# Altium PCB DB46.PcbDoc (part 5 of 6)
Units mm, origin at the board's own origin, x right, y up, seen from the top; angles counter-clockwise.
Board outline 82.2 x 113.2 mm, 8 copper layers (Top Layer, MidLayer1, MidLayer2, GND, MidLayer3, VCC, MidLayer4, Bottom Layer), stack 1.576 mm thick; 186 components, 477 nets, 1727 pads, 1538 vias.
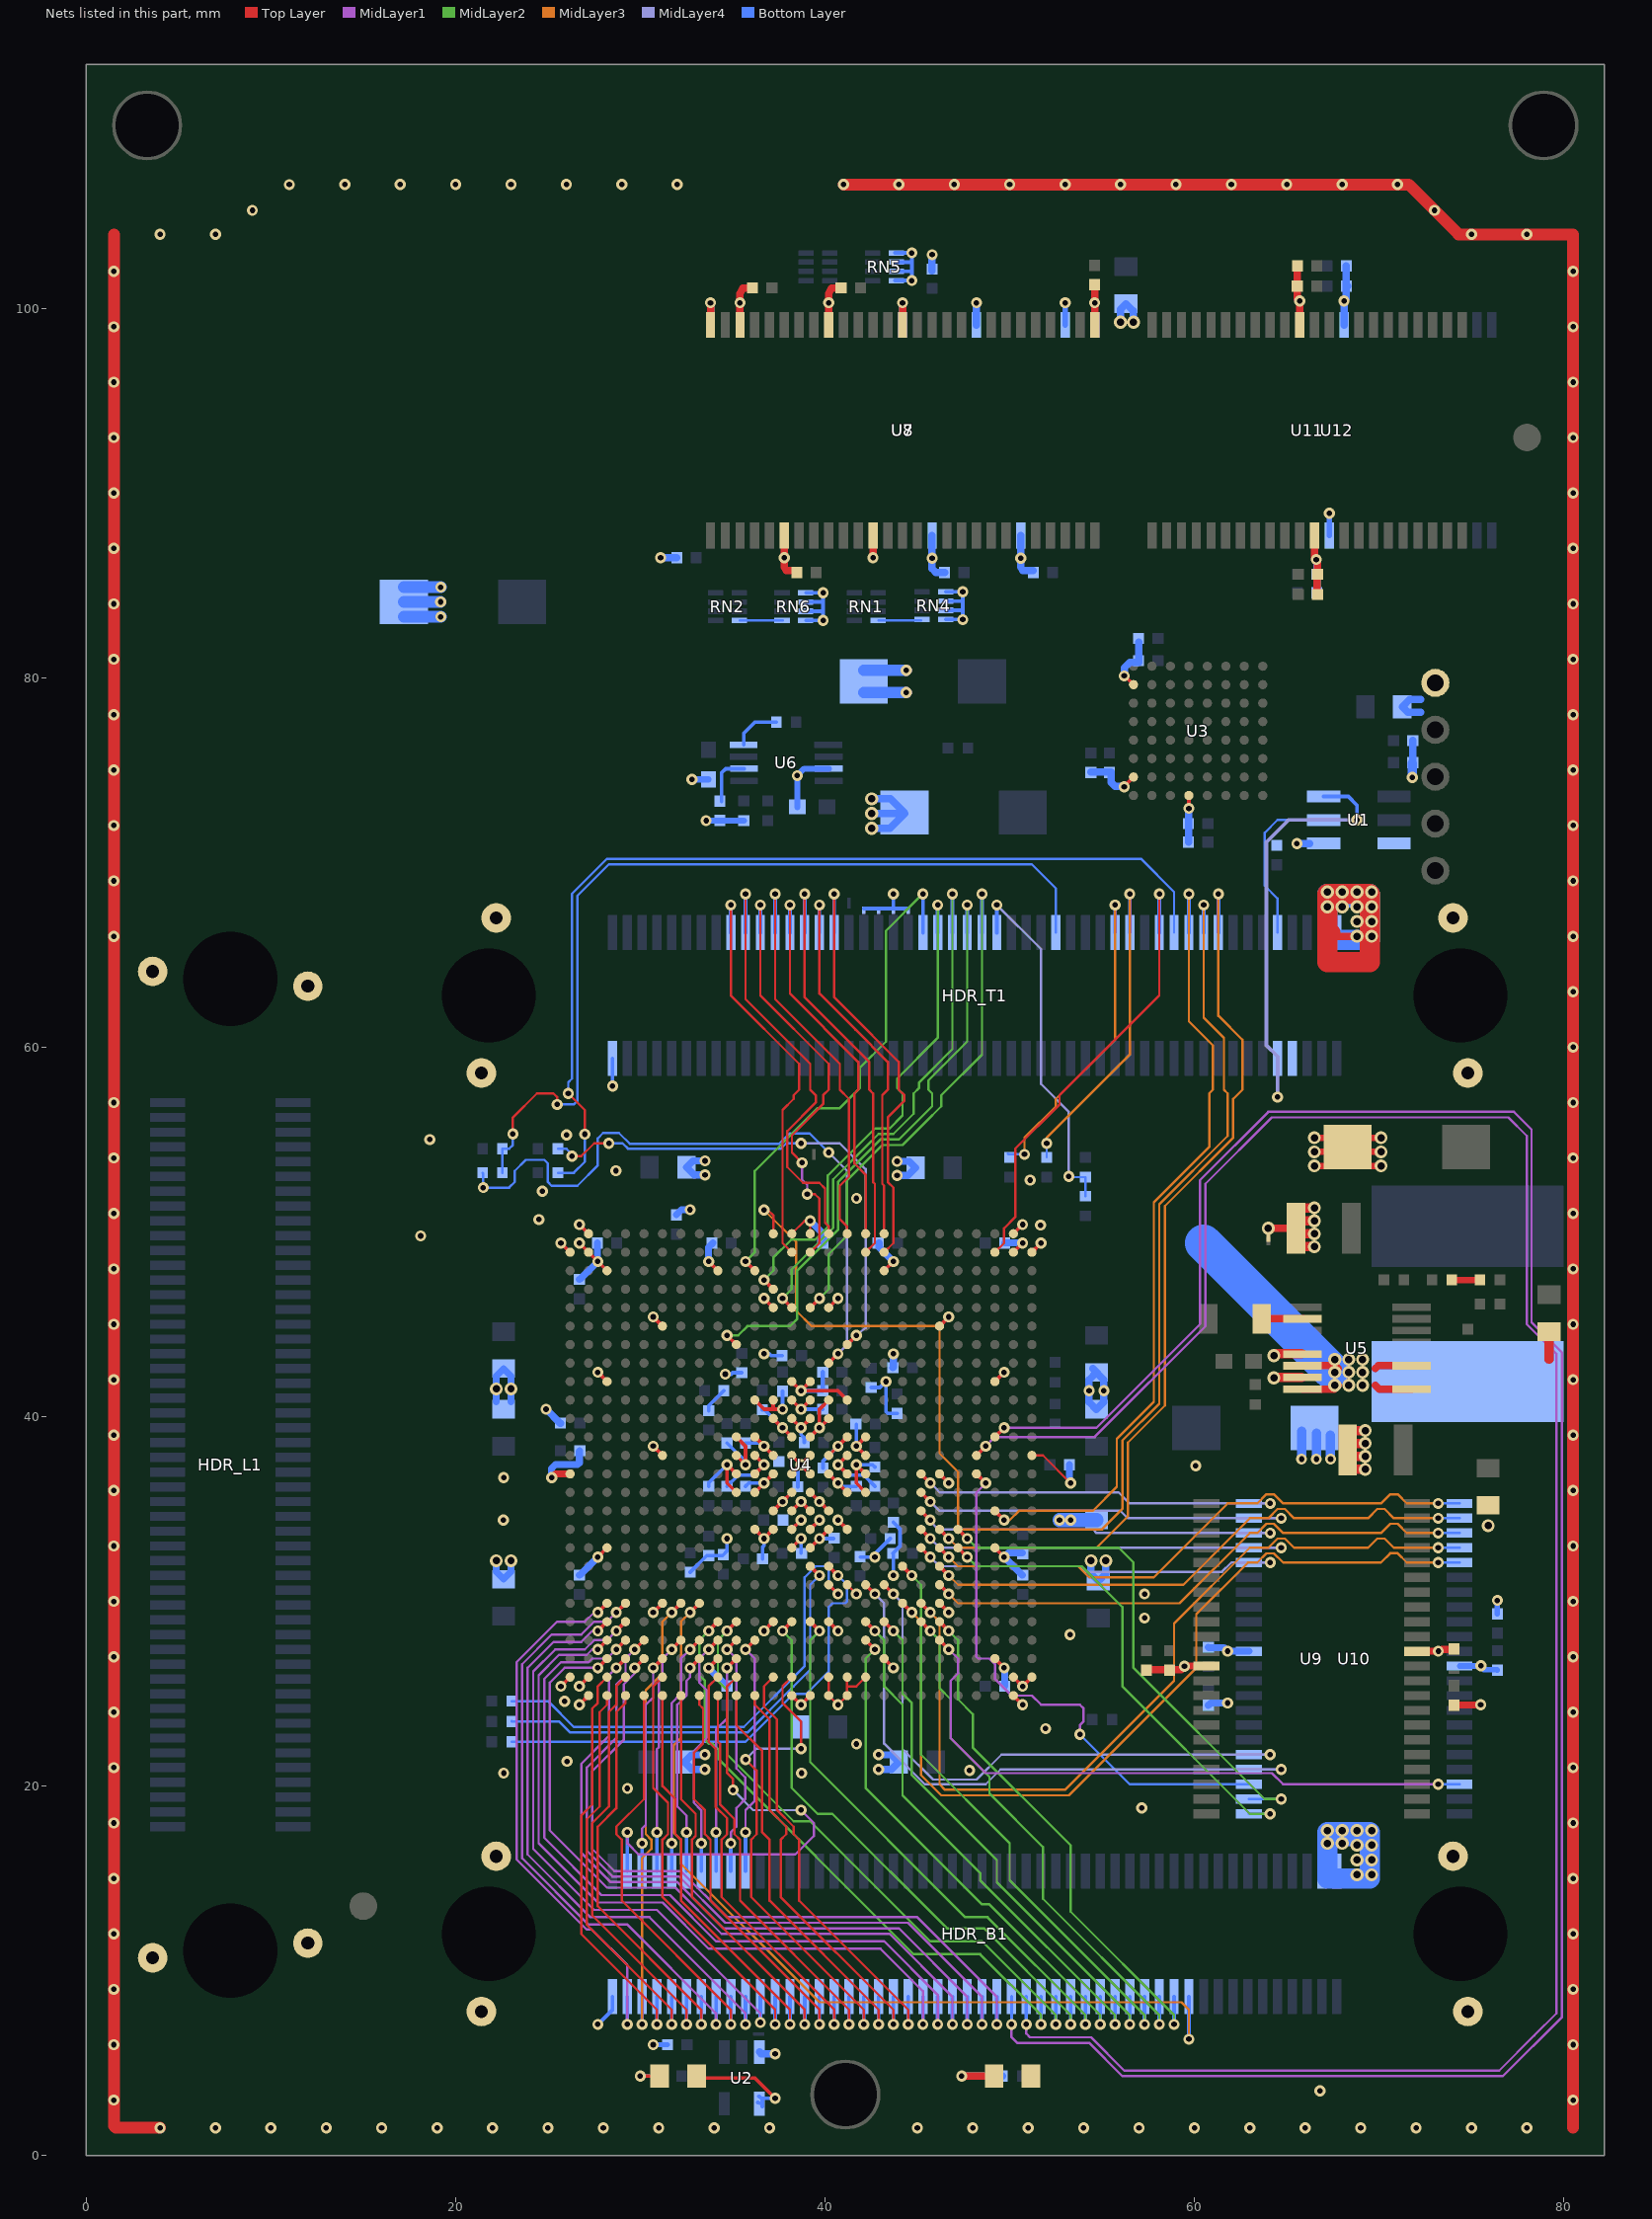
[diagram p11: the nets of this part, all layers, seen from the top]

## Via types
v1: diameter 0.6, hole 0.3, Top Layer to Bottom Layer, 904 vias
v2: diameter 0.6, hole 0.3, Top Layer to Bottom Layer, tented both sides, 506 vias
v3: diameter 0.7, hole 0.4, Top Layer to Bottom Layer, 127 vias
v4: diameter 0.6, hole 0.3, Top Layer to Bottom Layer, tented top, 1 vias

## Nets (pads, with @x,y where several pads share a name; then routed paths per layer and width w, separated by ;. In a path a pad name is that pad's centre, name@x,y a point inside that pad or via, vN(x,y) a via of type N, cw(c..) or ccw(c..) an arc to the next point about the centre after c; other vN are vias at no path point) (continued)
FPGA_PROGRAM: HDR_T1.62 R3.1 R15.1 | length 48.7
  Top Layer w0.127: v1(23.1,55.3) 23.1,56.2 24.4,57.5 25.3,57.5 25.5,57.3 v1(25.5,56.9)
  Bottom Layer w0.127: R15.1@22.538,53.2 R3.1@22.538,54.5 22.9,54.5 23.1,54.7 v1(23.1,55.3) ; v1(25.5,56.9) 26.4,56.9 26.6,57.1 26.6,68.2 28.3,69.9 51.2,69.9 52.5,68.6 HDR_T1.62@52.5,66.2
FPGA_TCK: HDR_T1.72 R7.1 | length 18.2
  MidLayer3 w0.127: v1(52,54.8) 52,55.1 52.3,55.4 ; 52.3,55.4 56.5,59.6 v2(56.5,68.3)
  Bottom Layer w0.127: R7.1@52,54.038 v1(52,54.8)
  Bottom Layer w0.2: HDR_T1.72@56.5,66.2 v2(56.5,68.3)
FPGA_TDI: HDR_T1.78 R10.1 | length 53
  Top Layer w0.127: v1(26.1,57.5) 27,56.6 v1(27,55.293)
  Bottom Layer w0.127: R10.1@25.538,53.2 26.4,53.2 27,53.8 v1(27,55.293) ; v1(26.1,57.5) 26.1,58.1 26.3,58.3 26.3,68.3 28.2,70.2 57.1,70.2 58.9,68.4 HDR_T1.78@58.9,66.2
FPGA_TDO: HDR_T1.54 R5.1 R9.1 | length 19.8
  MidLayer4 w0.127: v2(49.3,67.7) 51.7,65.3 51.7,58 53.2,56.5 v1(53.2,53)
  Bottom Layer w0.127: v1(53.2,53) 53.238,52.962 R5.1@54.1,52.962 R9.1@54.1,51.938
  Bottom Layer w0.2: HDR_T1.54@49.3,66.2 v2(49.3,67.7)
FPGA_TMS: HDR_T1.70 R6.1 | length 17.9
  MidLayer3 w0.127: v1(50.8,54.2) 50.8,55.1 52.5,56.8 52.5,57.2 55.7,60.4 v2(55.7,67.7)
  Bottom Layer w0.127: R6.1@49.9,54.238 49.938,54.2 50,54.2 v1(50.8,54.2)
  Bottom Layer w0.2: HDR_T1.70@55.7,66.2 v2(55.7,67.7)
GND: C1.1 C2.2 C3.2 C4.2 C5.2 C6.2 C7.2 C8.2 C9.2 C10.2 C11.2 C12.2 C13.2 C14.2 C15.2 C16.2 C17.2 C18.2 C19.2 C20.2 C21.2 C22.2 C23.2 C24.2 C25.2 C26.2 C27.2 C28.2 C29.2 C30.2 C31.2 C32.2 C33.2 C34.2 C35.2 C36.2 C37.2 C38.2 C39.2 C40.2 C41.2 C42.2 C43.2 C44.2 C45.2 C46.2 C47.2 C48.2 C49.2 C50.2 C51.2 C52.2 C53.2 C54.2 C55.2 C56.2 C57.2 C58.2 C59.2 C60.2 C61.2 C62.2 C63.2 C64.2 C65.2 C66.2 C67.2 C68.2 C69.2 C70.2 C71.1 C72.2 C73.2 C74.2 C75.2 C76.2 C77.2 C78.2 C79.2 C82.2 C83.2 C84.2 C85.2 C86.2 C88.2 C89.2 C90.2 C91.2 C92.2 C93.2 C94.2 C95.2 C96.2 C97.2 C98.2 C99.2 C100.2 C101.2 C102.2 C103.2 C104.2 C105.2 C106.2 C107.2 C108.2 C109.2 C110.2 C111.2 C112.2 C113.2 C114.2 HDR_B1.1 HDR_B1.98 HDR_B1.100 HDR_B1.MH1 HDR_B1.MH2 HDR_B1.MH3 HDR_B1.MH4 HDR_L1.MH1 HDR_L1.MH2 HDR_L1.MH3 HDR_L1.MH4 HDR_T1.1 HDR_T1.98 HDR_T1.100 HDR_T1.MH1 HDR_T1.MH2 HDR_T1.MH3 HDR_T1.MH4 LED2.2 NT3.2 NT5.2 NT6.2 NT7.2 NT8.2 R29.2 RN4.1 RN4.2 RN4.3 RN4.4 RN5.1 RN5.2 RN5.3 RN5.4 RN6.1 RN6.2 RN6.3 RN6.4 TP1.1 U1.1 U2.3 U3.E8 U3.H2 U3.H7 U4.A2 U4.A13 U4.A14 U4.A25 U4.AA6 U4.AA21 U4.AB12 U4.AB15 U4.AD9 U4.AD18 U4.AD24 U4.AE1 U4.AE2 U4.AE15 U4.AE16 U4.AE17 U4.AE25 U4.AE26 U4.AF2 U4.AF13 U4.AF14 U4.AF15 U4.AF16 U4.AF25 U4.B1 U4.B2 U4.B25 U4.B26 U4.C3 U4.C9 U4.C18 U4.E12 U4.E15 U4.F6 U4.F21 U4.J3 U4.J13 U4.J14 U4.J24 U4.K11 U4.K12 U4.K13 U4.K14 U4.K15 U4.K16 U4.L12 U4.L13 U4.L14 U4.L15 U4.M10 U4.M11 U4.M13 U4.M14 U4.M16 U4.M17 U4.N6 U4.N10 U4.N11 U4.N12 U4.N13 U4.N14 U4.N15 U4.N16 U4.N17 U4.N26 U4.P1 U4.P10 U4.P11 U4.P12 U4.P13 U4.P14 U4.P15 U4.P16 U4.P17 U4.P21 U4.R10 U4.R11 U4.R13 U4.R14 U4.R16 U4.R17 U4.T12 U4.T13 U4.T14 U4.T15 U4.U11 U4.U12 U4.U13 U4.U14 U4.U15 U4.U16 U4.V3 U4.V13 U4.V14 U4.V24 U4.Y16 U5.13 U5.15 U6.3 U7.6 U7.12 U7.28 U7.41 U7.46 U7.52 U7.54 U8.6 U8.12 U8.28 U8.41 U8.46 U8.52 U8.54 U9.12 U9.34 U10.12 U10.34 U11.12 U11.34 U12.12 U12.34 | length 594.7
  Top Layer w0.127: U4.A13@38.2,49.9 38.9,50.6 v1(39.2,50.6) U4.A14@39.2,49.9 ; U4.AE15@40.2,25.9 U4.AF15@40.2,24.9 v1(40.7,24.4) U4.AF16@41.2,24.9 ; U4.AF16@41.1,24.8 U4.AF16@41.2,24.9 ; 41.2,25.4 41.7,25.4 U4.AE17@42.2,25.9 ; U4.AE16@41.2,25.9 U4.AF16@41.2,24.9 ; U4.Y16@41.2,30.9 v2(41.7,30.4) ; U4.N26@51.2,37.9 51.8,37.9 v1(53.3,36.4)
  Top Layer w0.2: v1(25.7,25.4) U4.AE1@26.2,25.9 ; v1(25.7,49.4) U4.B1@26.2,48.9 ; v1(26.7,24.4) U4.AF2@27.2,24.9 ; v1(26.7,25.4) U4.AE2@27.2,25.9 ; v1(26.7,49.4) U4.C3@28.2,47.9 ; v1(26.7,50.4) U4.A2@27.2,49.9 ; v1(27.7,32.4) U4.V3@28.2,32.9 ; v1(27.7,42.4) U4.J3@28.2,41.9 ; v1(30.7,29.4) U4.AA6@31.2,29.9 ; v1(30.7,38.4) U4.N6@31.2,37.9 ; v1(30.7,45.4) U4.F6@31.2,44.9 ; v1(33.7,26.4) U4.AD9@34.2,26.9 ; v1(33.7,48.4) U4.C9@34.2,47.9 ; U4.R10@35.2,35.9 34.7,36.4 v1(34.7,37.4) U4.P10@35.2,36.9 ; U4.N10@35.2,37.9 v1(35.7,37.4) 35.7,38.4 U4.M10@35.2,38.9 ; U4.U11@36.2,33.9 v2(36.7,33.4) U4.U12@37.2,33.9 ; U4.R11@36.2,35.9 v1(36.7,36.4) U4.P12@37.2,36.9 ; U4.P11@36.2,36.9 v1(36.7,37.4) U4.N11@36.2,37.9 ; U4.M11@36.2,38.9 U4.N12@37.2,37.9 ; U4.K11@36.2,40.9 36.7,40.4 v2(37.7,40.4) ; v1(36.7,28.4) U4.AB12@37.2,28.9 ; v1(36.7,46.4) U4.E12@37.2,45.9 ; U4.T12@37.2,35 U4.T12@37.2,34.9 v1(37.7,35.4) U4.R13@38.2,35.9 ; U4.L12@37.2,39.9 U4.M13@38.2,38.9 ; 37.2,40.4 U4.K12@37.2,40.9 ; U4.AF13@38.2,24.9 v1(38.7,24.4) U4.AF14@39.2,24.9 ; U4.V13@38.2,32.9 v1(38.7,33.4) ; U4.U13@38.2,33.9 v1(38.7,34.4) ; U4.T13@38.2,34.9 v1(38.7,35.4) U4.T14@39.2,34.9 ; U4.L13@38.2,39.9 v1(38.7,39.4) U4.L14@39.2,39.9 ; U4.K13@38.2,40.9 v1(38.7,40.4) U4.K14@39.2,40.9 ; U4.J13@38.2,41.9 v1(38.7,41.4) ; U4.V14@39.2,32.9 v2(39.7,33.4) U4.U15@40.2,33.9 ; U4.U14@39.2,33.9 v2(39.7,34.4) ; U4.R14@39.2,35.9 v1(39.7,35.4) U4.T15@40.2,34.9 ; U4.M14@39.2,38.9 U4.L15@40.2,39.9 ; U4.J14@39.2,41.9 v1(38.7,41.4) ; v1(39.7,39.4) 39.7,40.4 U4.K15@40.2,40.9 ; U4.AB15@40.2,28.9 v1(40.7,28.4) ; U4.P15@40.2,36.9 v1(40.7,36.4) U4.R16@41.2,35.9 ; U4.N15@40.2,37.9 U4.M16@41.2,38.9 ; U4.E15@40.2,45.9 v1(40.7,46.4) ; v2(40.7,34.4) U4.U16@41.2,33.9 ; U4.P16@41.2,36.9 v1(40.7,37.4) U4.N16@41.2,37.9 ; U4.K16@41.2,40.9 40.7,41.4 v1(38.7,41.4) ; U4.R17@42.2,35.9 41.7,36.4 v1(41.7,37.4) U4.P17@42.2,36.9 ; U4.N17@42.2,37.9 v1(41.7,38.4) U4.M17@42.2,38.9 ; U4.AD18@43.2,26.9 v1(43.7,26.4) ; U4.C18@43.2,47.9 v1(43.7,48.4) ; U4.AA21@46.2,29.9 v1(46.7,29.4) ; U4.P21@46.2,36.9 v1(46.7,36.4) ; U4.F21@46.2,44.9 v1(46.7,45.4) ; U4.AD24@49.2,26.9 v1(49.7,26.4) ; U4.V24@49.2,32.9 v1(49.7,32.4) ; U4.J24@49.2,41.9 v1(49.7,42.4) ; U4.AF25@50.2,24.9 v1(50.7,24.4) ; U4.AE25@50.2,25.9 v1(50.7,25.4) U4.AE26@51.2,25.9 ; U4.B25@50.2,48.9 v1(50.7,49.4) ; U4.A25@50.2,49.9 v1(50.7,50.4) ; U4.B26@51.2,48.9 v1(51.7,49.4) ; v1@56.2,74.125 U3.H7@56.7,74.625 ; v1@56.2,80.125 56.213,80.113 U3.H2@56.7,79.625 ; v1(59.7,72.925) U3.E8@59.7,73.625
  Top Layer w0.203: U4.P13@38.2,36.9 U4.N14@39.2,37.9 ; U4.N13@38.2,37.9 U4.P14@39.2,36.9
  Top Layer w0.35: v3(66.5,53.576) C82.2@67.795,53.576 ; v3(66.5,54.338) C82.2@67.795,54.338 ; v3(66.5,55.1) C82.2@67.795,55.1 ; C82.2@68.809,53.576 v3(70.104,53.576) ; C82.2@68.809,54.338 v3(70.104,54.338) ; C82.2@68.809,55.1 v3(70.104,55.1)
  Top Layer w0.381: v1(25.2,36.7) 25.4,36.9 U4.P1@26.2,36.9 ; C102.2@57.4,26.275 57.425,26.3 59.3,26.3 59.461,26.461 v1(59.461,26.492) 59.469,26.5 U9.34@60.652,26.5 ; v3(64.3,42.1) v3@64.319,42.119 ; v3(64.3,43.3) v3@64.4,43.4 ; U9.12@72.052,27.3 73.198,27.3 v1(73.203,27.305) 73.305,27.305 73.4,27.4 74.027,27.4 C99.2@74.052,27.425 ; C101.2@74.049,24.331 74.1,24.327 74.027,24.4 v1(75.5,24.4)
  Top Layer w0.4: U7.54@33.8,99.1 v2(33.8,100.3) ; U7.52@35.4,99.1 v2(35.4,100.3) ; v2@35.4,100.2 35.4,100.7 ; 35.4,100.8 35.55,101.1 C95.2@36.075,101.1 ; C95.2@35.975,101.1 C95.2@36.025,101.05 ; U7.6@37.8,87.7 37.8,86.6 v2(37.8,86.5) 37.8,86 37.9,85.8 C92.2@38.475,85.8 ; U7.46@40.2,99.1 v2(40.2,100.3) ; v2@40.2,100.2 40.2,100.8 40.35,101.1 C96.2@40.875,101.1 ; v2(42.6,86.5) U7.12@42.6,87.7 ; U7.41@44.2,99.1 v2(44.2,100.3) ; U7.28@54.6,99.1 C91.2@54.6,101.275 ; v3(64,50.2) C86.2@65.6,50.2 ; C108.2@65.543,102.325 C108.2@65.546,102.328 ; C108.2@65.575,102.3 65.575,100.525 v2(65.7,100.4) U11.34@65.7,99.1 ; U11.12@66.5,87.7 66.5,86.5 v2(66.6,86.4) 66.668,86.332 C111.2@66.668,85.6 C111.2@66.693,85.625 ; C107.2@66.643,84.575 66.643,85.6 C111.2@66.644,85.604 ; 67.2,66 v3(68.8,66)
  Top Layer w0.5: 79.2,43.099 C85.2@79.2,44.6
  Top Layer w0.508: v3@64.319,42.119 U5.15@65.813,42.119 ; v3@64.4,43.4 U5.13@65.8,43.4 ; C86.2@65.5,49.2 v3(66.5,49.2) ; C86.2@65.5,49.9 v3(66.5,49.9) ; C86.2@65.5,50.6 v3(66.5,50.6) ; C86.2@65.5,51.3 v3(66.5,51.3) ; C84.2@68.25,37.15 v3(69.25,37.15) ; C84.2@68.25,37.85 v3(69.25,37.85) ; C84.2@68.25,38.55 v3(69.25,38.55) ; C84.2@68.25,39.25 v3(69.25,39.25)
  Top Layer w0.635: 1.5,104 1.5,1.6 1.6,1.5 v1(4,1.5) ; v1(41,106.7) 71.6,106.7 74.3,104 80.5,104 80.5,1.5
  Top Layer w1: 67.2,66.2 67.4,66.2
  Top Layer w1.1: 67.2,64.6 69.5,64.6 69.5,68.3 67.2,68.3 67.2,64.6
  Bottom Layer w0.2: v1@27.5,48.4 v1(27.7,48.4) v1@27.7,48.6 ; v2(27.7,7.1) 28.5,7.9 HDR_B1.1@28.5,8.6 ; v2(28.5,57.9) HDR_T1.1@28.5,59.4 ; C40.2@32.7,31.575 33.6,32.475 34.45,32.475 34.7,32.725 v2(34.7,33.4) ; C66.2@33.7,36.225 33.7,36.4 v1(34.7,37.4) ; C29.2@33.7,40.325 33.7,40.575 C53.2@34.525,41.4 ; C19.2@34.7,36.225 35.305,36.83 36.13,36.83 v1(36.7,37.4) ; C22.2@34.7,38.575 35.7,37.575 v1(35.7,37.4) ; C20.2@35.7,36.225 35.875,36.4 v1(36.7,36.4) ; C14.2@35.7,38.575 36.525,38.575 v1(36.7,38.4) ; C18.2@36.6,40.375 36.725,40.375 v1(37.7,39.4) ; C31.2@36.625,32.3 36.625,32.942 36.7,33.017 v2(36.7,33.4) ; C9.2@38.525,36.2 38.525,37.225 v1(38.7,37.4) ; C67.2@38.7,32.625 v1(38.7,33.4) ; v1(38.7,39.4) 38.7,39.024 38.875,38.849 C10.2@38.875,38.6 ; v1(38.7,40.4) C21.2@39.875,40.4 ; RN6.4@38.98,83.1 v1(39.9,83.1) v1(39.9,84.6) RN6.1@38.98,84.6 ; RN6.3@38.98,83.6 39.9,83.6 ; RN6.2@38.98,84.1 39.9,84.1 ; v2(39.7,33.4) C27.2@40.475,33.4 ; C15.2@39.9,37.225 39.9,37.6 v1(40.7,38.4) ; v1(40.7,36.4) 40.875,36.225 C8.2@41.7,36.225 ; v1(40.7,37.4) 40.705,37.4 41.275,36.83 42.095,36.83 C16.2@42.7,36.225 ; v1(41.7,37.4) 42.575,37.4 C26.2@42.7,37.275 ; v1(41.7,38.4) C17.2@41.7,39.575 ; C58.2@41.925,32.4 v1(42.7,32.4) 42.7,32.575 C7.2@43.525,33.4 ; NT7.2@42.1,67.5 NT3.2@44.5,67.5 ; C50.2@42.5,41.575 42.975,41.575 v1(43.3,41.9) 43.3,40.266 43.391,40.175 C52.2@43.9,40.175 ; C65.2@43.675,32.6 44.069,32.994 44.069,33.906 C30.2@43.7,34.275 ; NT5.2@43.7,67.5 v2(43.7,68.3) ; v2(43.7,31.4) C65.2@43.7,32.575 ; RN5.4@43.78,101.5 v1(44.7,101.5) v1(44.7,103) RN5.1@43.78,103 ; RN5.3@43.78,102 44.7,102 ; RN5.2@43.78,102.5 44.7,102.5 ; RN4.4@46.54,83.15 v1(47.46,83.15) v1(47.46,84.65) RN4.1@46.54,84.65 ; RN4.3@46.54,83.65 47.46,83.65 ; RN4.2@46.54,84.15 47.46,84.15
  Bottom Layer w0.203: v2(34.6,42.3) 34.934,42.3 35.009,42.375 C63.2@35.5,42.375 ; v2(36.7,43.4) 36.991,43.4 37.091,43.3 C61.2@37.675,43.3 ; v2(37.7,40.4) C28.2@37.7,41.375
  Bottom Layer w0.25: v1(30.7,6) C71.1@31.475,6
  Bottom Layer w0.254: v1(38.7,41.4) C12.2@39.875,41.4 C25.2@39.875,42.4
  Bottom Layer w0.3: U8.52@53,99.1 v2(53,100.3) ; U8.54@54.6,99.1 v2(54.6,100.3) ; U12.12@67.3,87.7 v2(67.3,88.9) ; U10.34@74.352,26.5 v1@75.496,26.5 ; v1(75.514,26.518) v1@75.496,26.5 ; C106.2@76.4,26.275 76.375,26.3 75.675,26.3 75.496,26.479 v1@75.496,26.5 ; C104.2@76.4,29.325 v1(76.4,30.05)
  Bottom Layer w0.33: v2(32.8,74.5) C89.2@33.7,74.5 ; v2(33.562,72.262) R29.2@35.6,72.262 ; C88.2@38.5,73 v2(38.5,74.7) 38.875,75.075 U6.3@40.2,75.075
  Bottom Layer w0.381: v3(22.2,32.2) 22.2,31.6 C35.2@22.6,31.2 23,31.6 v3(23,32.2) ; C4.2@22.2,40.8 C33.2@22.2,42.2 ; v3(22.2,41.5) C33.2@22.2,42.2 ; C4.2@23,40.8 C33.2@23,42.2 ; v3(23,41.5) C33.2@23,42.2 ; v1(25.2,36.7) 25.2,37.2 25.4,37.4 26.6,37.4 26.7,37.5 26.7,38.125 C55.2@26.724,38.15 ; C57.2@26.699,31.425 26.725,31.425 v1(27.7,32.4) ; C44.2@26.699,47.425 26.725,47.425 v1(27.7,48.4) ; v1@27.674,48.425 C68.2@27.674,49.4 ; C54.2@31.95,50.925 32.224,51.2 v1(32.7,51.2) ; v2(33.5,20.9) 32.8,20.9 C39.2@32.4,21.3 32.8,21.7 v2(33.5,21.7) ; v1(33.503,53.086) 33.5,53.083 32.917,53.083 C32.2@32.5,53.5 32.848,53.848 v1(33.503,53.848) ; v1(33.7,26.4) 34.676,25.424 C49.2@34.7,25.424 ; v1(33.7,48.4) 33.7,49.176 C47.2@33.925,49.4 ; v1(39.2,50.6) 39.925,49.875 C51.2@39.925,49.4 ; v1(42.9,20.9) 43.6,20.9 C38.2@44,21.3 43.6,21.7 v1(42.9,21.7) ; C43.2@42.925,49.4 42.925,49.175 v1(43.7,48.4) ; C41.2@43.675,42.65 43.7,42.675 v1(43.7,43.4) ; v1@43.9,52.961 v1(43.906,53.061) 44.489,53.061 C34.2@44.903,53.474 44.555,53.823 v1(43.906,53.823) ; C45.2@49.725,25.399 v1@49.725,26.374 ; C48.2@49.725,49.4 v1@50.699,49.4 ; C62.2@50.701,31.425 50.675,31.425 v1(49.7,32.4) 49.925,32.625 C64.2@50.701,32.625 ; C60.2@53.226,37.4 53.226,36.474 v1(53.3,36.4) ; C103.2@60.752,24.375 60.877,24.5 v1(61.8,24.5) ; C105.2@60.752,27.525 60.777,27.5 61.6,27.5 61.795,27.305 v1(61.798,27.305) 61.803,27.3 U10.12@62.952,27.3 ; C33.2@22.2,42.2 C33.2@22.6,42.6 C33.2@23,42.2
  Bottom Layer w0.4: v1(24.9,40.4) 25.65,39.65 C42.2@25.675,39.65 ; v2(31.1,86.5) C93.2@31.975,86.5 ; U8.28@33.8,99.1 v2@33.8,100.2 ; U2.3@36.45,5.6 36.55,5.5 v1(37.3,5.5) ; v3(42.525,71.85) 43.52,71.85 44.327,72.657 44.289,72.694 43.534,73.45 v3(42.525,73.45) ; v3(42.525,72.65) C70.2@44.32,72.65 ; U8.41@44.2,99.1 v2(44.2,100.3) ; U8.12@45.8,87.7 45.8,86.5 v2(45.8,86.475) 45.8,85.9 46,85.7 C98.2@46.475,85.7 ; C94.2@45.8,102.025 45.8,102.8 v2(45.8,102.9) ; U8.46@48.2,99.1 v2(48.2,100.3) ; U8.6@50.6,87.7 50.6,86 50.7,85.8 C97.2@51.275,85.8 ; v3(54.4,32.2) 54.4,31.5 C37.2@54.8,31.1 54.9,31.2 55.2,31.5 v3(55.2,32.2) ; C77.2@54.4,74.9 55.5,74.9 55.5,74.325 55.7,74.125 v1@56.2,74.125 ; C36.2@54.5,42.6 55.1,42 55.1,40.8 C6.2@54.7,40.4 54.3,40.8 54.3,42 C36.2@54.7,42.4 ; v3(56,99.25) 56,99.95 C79.2@56.3,100.25 56.7,99.85 v3(56.7,99.25) ; v1(56.2,80.1) 56.2,80.525 56.5,80.825 56.975,80.825 C73.2@56.975,81.925 ; C72.2@59.675,71.1 59.7,71.125 v1(59.7,72.925) ; v2(65.55,71.025) 66.245,71.025 U1.1@66.25,71.03 ; v2(66.6,86.4) 66.625,86.375 C109.2@66.625,84.6 ; v2@68.1,100.5 v2(68.1,100.4) 68.225,100.525 C114.2@68.225,101.2 ; U12.34@68.107,99.1 v2@68.107,100.2 ; C110.2@68.225,102.3 68.225,101.275 C114.2@68.3,101.2 ; C2.2@71.825,75.4 C1.1@71.825,76.6 ; 72.25,78.125 71.55,78.125 C78.2@71.25,78.425 71.65,78.825 72.25,78.825
  Bottom Layer w0.508: v1(65.8,37.7) C3.2@65.8,39.2 ; v1(66.6,37.7) C3.2@66.6,39.1 ; v1(67.369,37.7) C3.2@67.369,39 ; v2(71.8,74.6) C2.2@71.8,75.375
  Bottom Layer w0.635: C69.2@17.2,83.3 v2(19.2,83.3) ; C69.2@17.2,84.9 v2(19.2,84.9) ; C69.2@17.202,84.107 v2(19.193,84.107) ; C23.2@42.1,79.2 v2(44.4,79.2) ; C23.2@42.1,80.4 v2(44.4,80.4)
  Bottom Layer w0.762: v1(52.7,34.4) C5.2@54.701,34.4
  Bottom Layer w1.1: v3@67.3,17.3 v3@69.5,17.3 ; v3@67.3,68.1 v3@69.5,68.1 ; v3@69.5,68.1 69.5,68.3 67.2,68.3 67.2,65.8 69.5,65.8 69.5,66 69.5,66.8 69.5,67.6 v3@69.5,68.1 ; 67.2,15 69.5,15 69.5,15.2 69.5,16 69.5,16.8 69.5,17.5 67.2,17.5 67.2,15
  other v1: 7,1.5 10,1.5 13,1.5 16,1.5 19,1.5 22,1.5 25,1.5 28,1.5 31,1.5 34,1.5 37,1.5 45,1.5 48,1.5 51,1.5 54,1.5 57,1.5 60,1.5 63,1.5 66,1.5 69,1.5 72,1.5 75,1.5 78,1.5 1.5,3 80.5,3 66.8,3.5 1.5,6 80.5,6 1.5,9 80.5,9 1.5,12 80.5,12 1.5,15 80.5,15 1.5,18 80.5,18 57.15,18.821 29.304,19.873 22.606,20.701 38.735,20.701 47.828,20.853 1.5,21 80.5,21 26.035,21.336 41.707,22.276 51.943,23.114 1.5,24 80.5,24 25.903,24.595 1.5,27 80.5,27 53.264,28.194 57.3,29.1 1.5,30 80.5,30 57.3,30.4 1.5,33 80.5,33 22.583,34.404 53.3,34.4 1.5,36 80.5,36 22.606,36.703 60.071,37.338 1.5,39 80.5,39 54.3,41.4 55.1,41.4 1.5,42 80.5,42 1.5,45 80.5,45 1.5,48 80.5,48 18.11,49.784 51.664,50.368 24.511,50.673 1.5,51 80.5,51 41.707,51.816 51.105,52.807 28.677,53.315 1.5,54 80.5,54 26.01,55.245 1.5,57 80.5,57 80.5,60 80.5,63 1.5,66 80.5,66 1.5,69 80.5,69 1.5,72 80.5,72 56.2,74.1 1.5,75 80.5,75 1.5,78 80.5,78 1.5,81 80.5,81 1.5,84 80.5,84 1.5,87 80.5,87 1.5,90 80.5,90 1.5,93 80.5,93 1.5,96 80.5,96 1.5,99 80.5,99 1.5,102 80.5,102 4,104 7,104 75,104 78,104 9,105.3 73,105.3 10.996,106.695 14,106.7 17,106.7 20,106.7 23,106.7 26,106.7 29,106.7 32,106.7 44,106.7 47,106.7 50,106.7 53,106.7 56,106.7 59,106.7 62,106.7 65,106.7 68,106.7 71,106.7
  other v2: 24.7,52.2 18.6,55 50.6,86.475
  other v3: 68.8,15.2 69.6,15.2 68.8,16 69.6,16 68.8,16.8 69.6,16.8 67.2,16.9 68,16.9 67.2,17.6 68,17.6 68.8,17.6 69.6,17.6 75.9,34.1 69.6,66 68.8,66.8 69.6,66.8 67.2,67.6 68,67.6 68.8,67.6 69.6,67.6 67.2,68.4 68,68.4 68.8,68.4 69.6,68.4
HSWAP_EN: R4.2 U4.G16 | length 27.9
  Top Layer w0.127: v1(26.3,54.1) 26.8,54.1 27.5,54.8 v1(28.3,54.8)
  Top Layer w0.2: U4.G16@41.2,43.9 v1(41.7,44.4)
  MidLayer4 w0.127: v1(38.7,54.8) 40.8,54.8 42.2,53.4 42.2,48.7 42.2,44.8 v1(41.7,44.4)
  Bottom Layer w0.127: R4.2@25.538,54.5 26,54.5 26.3,54.2 v1(26.3,54.1) ; v1(28.3,54.8) 29.04,54.8 29.329,54.511 37.61,54.511 37.899,54.8 v1(38.7,54.8)
IO0: HDR_B1.7 U4.AE3 | length 22.6
  Top Layer w0.127: U4.AE3@28.2,25.9 27.7,25.4 27.7,24.5 27.4,24.2 27.4,23.3 27.4,23 27.4,19 26.8,18.4 26.8,12 30.9,7.9 v2(30.9,7.1)
  Bottom Layer w0.2: v2(30.9,7.1) HDR_B1.7@30.9,8.6
IO1: HDR_B1.9 U4.AF3 | length 21.7
  Top Layer w0.127: U4.AF3@28.2,24.9 28.2,24.4 27.8,24 27.8,23.3 27.8,23 27.8,18.9 27.1,18.2 27.1,12.5 31.7,7.9 v2(31.7,7.1)
  Bottom Layer w0.2: v2(31.7,7.1) HDR_B1.9@31.7,8.6
IO2: HDR_B1.11 U4.AE4 | length 23.2
  Top Layer w0.127: U4.AE4@29.2,25.9 28.7,25.4 28.7,24.4 28.3,24 28.3,23.3 28.3,23 28.3,18.9 27.4,18 27.4,13 32.5,7.9 v2(32.5,7.1)
  Bottom Layer w0.2: v2(32.5,7.1) HDR_B1.11@32.5,8.6
IO3: HDR_B1.13 U4.AF4 | length 22.2
  Top Layer w0.127: U4.AF4@29.2,24.9 29.2,24.5 28.7,24 28.7,23.3 28.7,23 28.7,18.8 27.7,17.8 27.7,13.5 33.3,7.9 v2(33.3,7.1)
  Bottom Layer w0.2: v2(33.3,7.1) HDR_B1.13@33.3,8.6
IO4: HDR_B1.15 U4.AA4 | length 33.5
  Top Layer w0.2: v1(28.7,29.4) U4.AA4@29.2,29.9
  MidLayer1 w0.127: v1(28.7,29.4) 28.2,28.9 27.5,28.9 26.8,28.2 25.2,28.2 23.6,26.6 23.6,16.1 27.2,12.5 29.3,12.5 34.1,7.7 v2(34.1,7.1)
  Bottom Layer w0.2: v2(34.1,7.1) HDR_B1.15@34.1,8.6
IO5: HDR_B1.17 U4.AF5 | length 22.5
  Top Layer w0.127: U4.AF5@30.2,24.9 30.2,24.4 30.2,23.3 30.2,23 30.2,19.3 28.7,17.8 28.7,17.4 29,17.1 29,13.8 34.9,7.9 v2(34.9,7.1)
  Bottom Layer w0.2: v2(34.9,7.1) HDR_B1.17@34.9,8.6
IO6: HDR_B1.19 U4.AB3 | length 32.9
  Top Layer w0.2: v1(27.7,28.4) U4.AB3@28.2,28.9
  MidLayer1 w0.127: v1(27.7,28.4) 27.4,28.4 26.8,27.8 25.3,27.8 23.9,26.4 23.9,16.3 27.3,12.9 30.5,12.9 35.7,7.7 v2(35.7,7.1)
  Bottom Layer w0.2: v2(35.7,7.1) HDR_B1.19@35.7,8.6
IO7: HDR_B1.21 U4.AB4 | length 33.8
  Top Layer w0.2: v1(28.7,28.4) U4.AB4@29.2,28.9
  MidLayer1 w0.127: v1(28.7,28.4) 28.2,27.9 27.5,27.9 27,27.4 25.4,27.4 24.2,26.2 24.2,16.6 27.5,13.3 30.9,13.3 36.5,7.7 v2@36.5,7.1
  Bottom Layer w0.2: v2@36.5,7.1 HDR_B1.21@36.5,8.6
  other v2: 36.5,7.2
IO8: HDR_B1.23 U4.AE6 | length 23.5
  Top Layer w0.127: U4.AE6@31.2,25.9 30.7,25.4 30.7,25.3 30.7,23.3 30.7,23 30.7,19.9 31.5,19.1 31.5,17.4 31.2,17.1 31.2,14 37.3,7.9 v2(37.3,7.1)
  Bottom Layer w0.2: v2(37.3,7.1) HDR_B1.23@37.3,8.6
IO9: HDR_B1.25 U4.AF6 | length 22.2
  Top Layer w0.127: U4.AF6@31.2,24.9 31.2,23.3 31.2,23 31.2,20 31.9,19.3 31.9,17.4 32.2,17.1 32.2,13.8 38.1,7.9 v2(38.1,7.1)
  Bottom Layer w0.2: v2(38.1,7.1) HDR_B1.25@38.1,8.6
IO10: HDR_B1.27 U4.AF7 | length 22.2
  Top Layer w0.127: U4.AF7@32.2,24.9 32.2,23.3 32.2,23 32.2,19.3 33,18.5 33,17.3 32.8,17.1 32.8,14 38.9,7.9 v2(38.9,7.1)
  Bottom Layer w0.2: v2(38.9,7.1) HDR_B1.27@38.9,8.6
IO11: HDR_B1.29 U4.AF8 | length 22.4
  Top Layer w0.127: U4.AF8@33.2,24.9 33.2,24.4 33.4,24.2 33.4,23.3 33.4,23 33.4,22.3 32.9,21.8 32.9,19.3 33.5,18.7 33.5,17.4 33.8,17.1 33.8,13.8 39.7,7.9 v2(39.7,7.1)
  Bottom Layer w0.2: v2(39.7,7.1) HDR_B1.29@39.7,8.6
IO12: HDR_B1.31 U4.AE9 | length 23.6
  Top Layer w0.127: U4.AE9@34.2,25.9 33.7,25.4 33.7,23.3 33.7,23 33.7,22.4 34.072,22.028 34.072,18.883 34.7,18.255 34.7,17.4 34.4,17.1 34.4,14 40.5,7.9 v2(40.5,7.1)
  Bottom Layer w0.2: v2(40.5,7.1) HDR_B1.31@40.5,8.6
IO13: HDR_B1.33 U4.AF9 | length 22.2
  Top Layer w0.127: U4.AF9@34.2,24.9 34.2,23.3 34.2,23 34.2,22.4 34.326,22.274 34.326,18.989 35.1,18.214 35.1,17.4 35.4,17.1 35.4,13.8 41.3,7.9 v2(41.3,7.1)
  Bottom Layer w0.2: v2(41.3,7.1) HDR_B1.33@41.3,8.6
IO14: HDR_B1.35 U4.AE13 | length 26.5
  Top Layer w0.127: v1(35.702,21.438) 36.3,20.84 36.3,17.4 36,17.1 36,14 42.1,7.9 v2(42.1,7.1) ; U4.AE13@38.2,25.9 37.7,25.4 37.7,24.5 38.699,23.5 v1(38.699,22.022)
  MidLayer4 w0.127: v1(35.702,21.438) 36.292,22.027 v1(38.699,22.022)
  Bottom Layer w0.2: v2(42.1,7.1) HDR_B1.35@42.1,8.6
IO15: HDR_B1.37 U4.AF10 | length 22.5
  Top Layer w0.127: U4.AF10@35.2,24.9 35.2,23.3 36.6,21.9 36.6,17.5 37,17.1 37,13.8 42.9,7.9 v2(42.9,7.1)
  Bottom Layer w0.2: v2(42.9,7.1) HDR_B1.37@42.9,8.6
IO16: HDR_B1.39 U4.AF11 | length 22.7
  Top Layer w0.127: U4.AF11@36.2,24.9 36.2,24.4 37,23.6 37,22.9 37,22.6 37,18.7 37.9,17.8 37.9,17.4 37.6,17.1 37.6,14 43.7,7.9 v2(43.7,7.1)
  Bottom Layer w0.2: v2(43.7,7.1) HDR_B1.39@43.7,8.6
IO17: HDR_B1.41 U4.AE12 | length 23.7
  Top Layer w0.127: U4.AE12@37.2,25.9 36.7,25.4 36.7,24.3 37.4,23.6 37.4,22.9 37.4,22.6 37.4,18.7 38.3,17.8 38.3,17.4 38.6,17.1 38.6,13.8 44.5,7.9 v2(44.5,7.1)
  Bottom Layer w0.2: v2(44.5,7.1) HDR_B1.41@44.5,8.6
IO18: HDR_B1.43 U4.AC3 | length 41
  Top Layer w0.2: v1(27.7,27.4) U4.AC3@28.2,27.9
  MidLayer1 w0.127: v1(27.7,27.4) 27.4,27.4 27.1,27.1 25.6,27.1 24.5,26 24.5,16.9 27.7,13.7 31.2,13.7 33.7,11.2 43,11.2 45.3,8.9 v2(45.3,7.1)
  Bottom Layer w0.2: v2(45.3,7.1) HDR_B1.43@45.3,8.6
IO19: HDR_B1.45 U4.AC4 | length 41.8
  Top Layer w0.2: v1(28.7,27.4) U4.AC4@29.2,27.9
  MidLayer1 w0.127: v1(28.7,27.4) 28.2,26.9 27.4,26.9 27.2,26.7 25.7,26.7 24.8,25.8 24.8,17.2 27.9,14.1 31.6,14.1 34.1,11.6 43.2,11.6 46.1,8.7 v2(46.1,7.1)
  Bottom Layer w0.2: v2(46.1,7.1) HDR_B1.45@46.1,8.6
IO20: HDR_B1.47 U4.AD3 | length 40.6
  Top Layer w0.2: v1(27.7,26.4) U4.AD3@28.2,26.9
  MidLayer1 w0.127: v1(27.7,26.4) 25.9,26.4 25.1,25.6 25.1,17.6 28.2,14.5 31.9,14.5 34.4,12 43.5,12 46.9,8.6 v2(46.9,7.1)
  Bottom Layer w0.2: v1@27.5,26.4 v1(27.7,26.4) v1@27.7,26.2 ; v2(46.9,7.1) HDR_B1.47@46.9,8.6
IO21: HDR_B1.49 U4.AD4 | length 38.6
  Top Layer w0.2: v1(28.7,26.4) U4.AD4@29.2,26.9
  MidLayer1 w0.127: v1(28.7,26.4) 28.3,26 28.3,23.3 28.3,23 28.3,22.7 26.8,21.2 26.8,16.4 28.4,14.8 32,14.8 34.5,12.3 44,12.3 47.7,8.6 v2(47.7,7.1)
  Bottom Layer w0.2: v2(47.7,7.1) HDR_B1.49@47.7,8.6
IO22: HDR_B1.51 U4.AC5 | length 40.4
  Top Layer w0.2: v1(29.7,27.4) U4.AC5@30.2,27.9
  MidLayer1 w0.127: v1(29.7,27.4) 29.2,26.9 29.2,26 28.7,25.5 28.7,23.3 28.7,23 28.7,22.6 27.1,21 27.1,16.5 28.5,15.1 32.1,15.1 34.6,12.6 44.5,12.6 48.5,8.6 v2(48.5,7.1)
  Bottom Layer w0.2: v2(48.5,7.1) HDR_B1.51@48.5,8.6
IO23: HDR_B1.53 U4.AD5 | length 39.7
  Top Layer w0.2: v1(29.7,26.4) U4.AD5@30.2,26.9
  MidLayer1 w0.127: v1(29.7,26.4) 29.7,26.1 29.1,25.5 29.1,23.3 29.1,23 29.1,22.5 27.4,20.8 27.4,16.6 28.6,15.4 32.2,15.4 34.7,12.9 45,12.9 49.3,8.6 v2(49.3,7.1)
  Bottom Layer w0.2: v2(49.3,7.1) HDR_B1.53@49.3,8.6
IO24: HDR_B1.55 U4.M24 | length 124.2
  Top Layer w0.2: U4.M24@49.2,38.9 v1(49.7,39.4)
  MidLayer1 w0.127: v1(49.7,39.4) 52.8,39.4 53.1,39.4 54.7,39.4 60.3,45 60.3,52.8 64,56.5 77.3,56.5 78.254,55.546 78.254,45.105 79.9,43.459 79.9,7.5 76.7,4.3 56.1,4.3 54.3,6.1 50.4,6.1 50.1,6.4 v2(50.1,7.1)
  Bottom Layer w0.178: v2(50.1,7.1) HDR_B1.55@50.1,8.6
IO25: HDR_B1.57 U4.N23 | length 123.3
  Top Layer w0.2: U4.N23@48.2,37.9 v1(48.7,38.4)
  MidLayer1 w0.127: v1(48.7,38.4) 49.2,38.9 52.8,38.9 53.1,38.9 54.6,38.9 60.6,44.9 60.6,52.6 64.2,56.2 77,56.2 78,55.2 78,45 79.6,43.4 79.6,7.7 78.4,6.5 76.5,4.6 56.2,4.6 54.4,6.4 51.1,6.4 50.9,6.6 v2(50.9,7.1)
  Bottom Layer w0.178: v2(50.9,7.1) HDR_B1.57@50.9,8.6
IO26: HDR_B1.59 U4.AB9 | length 33.6
  Top Layer w0.2: v1(33.7,28.4) U4.AB9@34.2,28.9
  MidLayer2 w0.127: v1(33.7,28.4) 33.2,27.9 33.2,26 33.5,25.7 33.5,23.3 33.5,23 33.5,22.5 33.7,22.3 33.9,22.3 34.25,21.95 34.25,21.45 44.8,10.9 48.4,10.9 51.7,7.6 v2(51.7,7.1)
  Bottom Layer w0.2: v2(51.7,7.1) HDR_B1.59@51.7,8.6
IO27: HDR_B1.61 U4.AB10 | length 33.5
  Top Layer w0.2: v1(34.7,28.4) U4.AB10@35.2,28.9
  MidLayer2 w0.127: v1(34.7,28.4) 34.2,27.9 34.2,25.7 34.7,25.2 34.7,23.3 34.7,23 34.7,21.7 38.3,18.1 39.2,18.1 45.7,11.6 48.5,11.6 52.5,7.6 v2(52.5,7.1)
  Bottom Layer w0.2: v2(52.5,7.1) HDR_B1.61@52.5,8.6
IO28: HDR_B1.63 U4.AB13 | length 31.6
  Top Layer w0.2: v1(37.7,28.4) U4.AB13@38.2,28.9
  MidLayer2 w0.127: v1(37.7,28.4) 38.2,27.9 38.2,19.9 39.6,18.5 40.4,18.5 46.6,12.3 48.6,12.3 53.3,7.6 v2(53.3,7.1)
  Bottom Layer w0.2: v2(53.3,7.1) HDR_B1.63@53.3,8.6
IO29: HDR_B1.65 U4.AB14 | length 30.6
  Top Layer w0.2: U4.AB14@39.2,28.9 v1(39.7,28.4)
  MidLayer2 w0.127: v1(39.7,28.4) 39.2,27.9 39.2,23.3 39.2,23 39.2,21.3 47.6,12.9 48.8,12.9 54.1,7.6 v2(54.1,7.1)
  Bottom Layer w0.2: v2(54.1,7.1) HDR_B1.65@54.1,8.6
IO30: HDR_B1.67 U4.AC17 | length 28.2
  Top Layer w0.2: U4.AC17@42.2,27.9 v1(42.7,27.4)
  MidLayer2 w0.127: v1(42.7,27.4) 42.2,26.9 42.2,23.3 42.2,23 42.2,19.9 48.5,13.6 48.9,13.6 54.9,7.6 v2(54.9,7.1)
  Bottom Layer w0.2: v2(54.9,7.1) HDR_B1.67@54.9,8.6
IO31: HDR_B1.69 U4.AB17 | length 28.9
  Top Layer w0.2: U4.AB17@42.2,28.9 v1(42.7,28.4)
  MidLayer2 w0.127: v1(42.7,28.4) 43.2,27.9 43.2,25.4 44.2,24.4 44.2,23.3 44.2,23 44.2,19.5 48.4,15.3 48.4,14.9 55.7,7.6 v2(55.7,7.1)
  Bottom Layer w0.2: v2(55.7,7.1) HDR_B1.69@55.7,8.6
IO32: HDR_B1.71 U4.AB18 | length 28.8
  Top Layer w0.2: U4.AB18@43.2,28.9 v1(43.7,28.4)
  MidLayer2 w0.127: v1(43.7,28.4) 44.2,27.9 44.2,25 44.7,24.5 44.7,23.3 44.7,23 44.7,20.6 49.3,16 49.3,14.8 56.5,7.6 v2(56.5,7.1)
  Bottom Layer w0.2: v2(56.5,7.1) HDR_B1.71@56.5,8.6
IO33: HDR_B1.73 U4.W19 | length 31.7
  Top Layer w0.2: U4.W19@44.2,31.9 v1(44.7,31.4)
  MidLayer2 w0.127: v1(44.7,31.4) 45.2,30.9 45.2,23.3 45.2,23 45.2,21.7 50,16.9 50,14.9 57.3,7.6 v2(57.3,7.1)
  Bottom Layer w0.2: v2(57.3,7.1) HDR_B1.73@57.3,8.6
IO34: HDR_B1.75 U4.AB20 | length 28.6
  Top Layer w0.2: U4.AB20@45.2,28.9 v1(45.7,28.4)
  MidLayer2 w0.127: v1(45.7,28.4) 46.2,27.9 46.2,25.3 46.8,24.7 46.8,23.3 46.8,23 46.8,22.6 48.9,20.5 48.9,19.6 51.8,16.7 51.8,13.9 58.1,7.6 v2(58.1,7.1)
  Bottom Layer w0.2: v2(58.1,7.1) HDR_B1.75@58.1,8.6
IO35: HDR_B1.77 U4.AB21 | length 28.6
  Top Layer w0.2: U4.AB21@46.2,28.9 v1(46.7,28.4)
  MidLayer2 w0.127: v1(46.7,28.4) 47.2,27.9 47.2,24.7 48,23.9 48,23.3 48,23 48,22.1 53.3,16.8 53.3,13.2 58.9,7.6 v2(58.9,7.1)
  Bottom Layer w0.2: v2(58.9,7.1) HDR_B1.77@58.9,8.6
KBCLOCK: HDR_T1.26 U4.A17 | length 21.2
  Top Layer w0.127: v2(38.1,67.7) 38.1,62.9 41.8,59.2 41.8,57.7 41.6,57.5 41.6,53.7 42.2,53.1 42.2,51.8 42.2,51.5 U4.A17@42.2,49.9
  Bottom Layer w0.2: HDR_T1.26@38.1,66.2 v2(38.1,67.7)
KBDATA: HDR_T1.28 U4.B17 | length 23.3
  Top Layer w0.127: v2(38.9,68.3) 38.9,63.9 38.9,62.7 42.4,59.2 42.4,57.7 42.6,57.5 42.6,52.7 42.7,52.6 42.7,51.8 42.7,51.5 42.7,49.4 U4.B17@42.2,48.9
  Bottom Layer w0.2: HDR_T1.28@38.9,66.2 v2(38.9,68.3)
LED0: HDR_B1.6 U4.AD6 | length 12
  Top Layer w0.2: v1(30.7,26.4) U4.AD6@31.2,26.9
  MidLayer1 w0.127: v2(30.1,16.9) 30.1,17.7 30.3,17.9 30.3,23 30.3,23.3 30.3,24.4 30.7,24.8 v1(30.7,26.4)
  Bottom Layer w0.2: HDR_B1.6@30.1,15.4 v2(30.1,16.9)
LED1: HDR_B1.8 U4.AC7 | length 13
  Top Layer w0.2: v1(31.7,27.4) U4.AC7@32.2,27.9
  MidLayer1 w0.127: v2(30.9,17.5) 30.9,22 31,22.1 31,23 31,23.3 31,25.8 31.2,26 31.2,26.9 v1(31.7,27.4)
  Bottom Layer w0.2: HDR_B1.8@30.9,15.4 v2(30.9,17.5)
LED2: HDR_B1.10 U4.AC8 | length 13.1
  Top Layer w0.2: v1(32.7,27.4) U4.AC8@33.2,27.9
  MidLayer1 w0.127: v2(31.7,16.9) 31.7,23 31.7,23.3 31.7,24.5 32.2,25 32.2,26.9 v1(32.7,27.4)
  Bottom Layer w0.2: HDR_B1.10@31.7,15.4 v2(31.7,16.9)
LED3: HDR_B1.12 U4.AD8 | length 12.2
  Top Layer w0.2: v1(32.7,26.4) U4.AD8@33.2,26.9
  MidLayer1 w0.127: v2(32.5,17.5) 32.5,18.4 32,18.9 32,23 32,23.3 32,24.4 32.5,24.9 32.5,25.7 32.7,25.9 v1(32.7,26.4)
  Bottom Layer w0.2: HDR_B1.12@32.5,15.4 v2(32.5,17.5)
LED4: HDR_B1.14 U4.AC9 | length 13.5
  Top Layer w0.2: v1(33.7,27.4) U4.AC9@34.2,27.9
  MidLayer1 w0.127: v2(33.3,16.9) 33.3,18.7 32.9,19.1 32.9,21.9 33.6,22.6 33.6,23 33.6,23.3 33.6,25.2 33.2,25.6 33.2,26.9 v1(33.7,27.4)
  Bottom Layer w0.2: HDR_B1.14@33.3,15.4 v2(33.3,16.9)
LED5: HDR_B1.16 U4.AD10 | length 12
  Top Layer w0.2: v1(34.7,26.4) U4.AD10@35.2,26.9
  MidLayer1 w0.127: v2(34.1,17.5) 34.1,23.068 34.7,23.668 34.7,24 v1(34.7,26.4)
  Bottom Layer w0.2: HDR_B1.16@34.1,15.4 v2(34.1,17.5)
LED6: HDR_B1.18 U4.AC10 | length 13.4
  Top Layer w0.2: v1(34.7,27.4) U4.AC10@35.2,27.9
  MidLayer1 w0.127: v1(34.7,27.4) 35.2,26.9 35.2,23.3 35.2,23 35.2,20.955 35.677,20.478 35.677,19.286 35.2,18.809 35.2,17.8 34.9,17.5 v2(34.9,16.9)
  Bottom Layer w0.2: HDR_B1.18@34.9,15.4 v2(34.9,16.9)
LED7: HDR_B1.20 U4.AC11 | length 13.1
  Top Layer w0.2: v1(35.7,27.4) U4.AC11@36.2,27.9
  MidLayer1 w0.127: v2(35.7,17.5) 35.7,18.7 36.2,19.2 36.2,23 36.2,23.3 36.2,26.9 v1(35.7,27.4)
  Bottom Layer w0.2: HDR_B1.20@35.7,15.4 v2(35.7,17.5)
LED_PGM: LED1.2 U2.4 | length 6.6
  Top Layer w0.2: LED1.2@32.9,4.2 33.05,4.2 36.2,4.2 v1(37.3,3.1)
  Bottom Layer w0.2: U2.4@36.36,2.869 36.462,2.833 36.6,2.785 36.6,2.65 36.6,2.8 U2.4@36.6,3.1 ; U2.4@36.4,3.2 36.45,3.2 36.55,3.1 v1(37.3,3.1)
LED_PWR: LED2.1 R2.2 | length 4.2
  Top Layer w0.4: v1(47.4,4.3) LED2.1@49.4,4.3
  Bottom Layer w0.4: v1(47.4,4.3) R2.2@49.612,4.3
LX: L1.1 U5.1 U5.3 U5.14 U5.16 | length 18.5
  Top Layer w0.4: U5.16@65.852,41.484 v3@67.584,41.484 ; U5.14@65.852,42.754 67.345,42.754 ; 67.4,42.7 67.345,42.754 ; v3@67.8,42.6 67.645,42.754 67.345,42.754 ; 69.8,41.7 70.015,41.484 U5.1@71.744,41.484 ; U5.3@71.744,42.754 69.954,42.754 ; v3@67.584,41.484 67.8,41.7 v3@67.584,41.484 ; 69.954,42.754 69.8,42.6 69.954,42.754
  Bottom Layer w2: 60.5,49.4 v3@67.4,42.5
  other v3: 67.6,41.7 68.35,41.7 69.101,41.7 67.6,42.4 68.35,42.4 69.101,42.4 67.6,43.1 68.35,43.1 69.101,43.1
M0: R14.2 U4.W15 | length 25.7
  Top Layer w0.2: U4.W15@40.2,31.9 v1(40.7,31.4)
  Bottom Layer w0.127: R14.2@23.038,22.4 35.7,22.4 38.3,25 39,25 40.2,26.2 40.2,29.7 40.4,29.9 41.1,29.9 41.2,30 41.2,30.9 v1(40.7,31.4)
M1: R13.2 U4.Y15 | length 26.5
  Top Layer w0.178: U4.Y15@40.2,30.9 v1(40.7,30.4)
  Bottom Layer w0.127: R13.2@23.038,24.6 25,24.6 26.4,23.2 35.6,23.2 38.9,26.5 38.9,31.3 39.5,31.9 40,31.9 40.2,31.7 40.2,30.9 v1(40.7,30.4)
M2: R12.2 U4.W14 | length 23.9
  Top Layer w0.2: U4.W14@39.2,31.9 v1(39.7,31.4)
  Bottom Layer w0.127: R12.2@23.038,23.538 R12.2@23.038,23.5 25.6,23.5 26.2,22.9 35.8,22.9 38.3,25.4 39.2,26.3 39.2,27.153 39.2,30.9 v1(39.7,31.4)
MOUSECLOCK: HDR_T1.30 U4.A18 | length 21
  Top Layer w0.127: v2(39.7,67.7) 39.7,62.9 41.65,60.949 43.4,59.2 43.4,57.7 43.1,57.4 43.1,52.6 43.2,52.5 43.2,51.8 43.2,51.5 U4.A18@43.2,49.9
  Bottom Layer w0.2: HDR_T1.30@39.7,66.2 v2(39.7,67.7)
MOUSEDATA: HDR_T1.32 U4.B18 | length 23.8
  Top Layer w0.127: v2(40.5,68.3) 40.5,62.7 41.147,62.053 44,59.2 44,57.7 44.3,57.4 44.3,57.1 43.4,56.2 43.4,52.7 43.7,52.4 43.7,51.8 43.7,51.5 43.7,49.4 U4.B18@43.2,48.9
  Bottom Layer w0.2: HDR_T1.32@40.5,66.2 v2(40.5,68.3)
NetC90_1: C90.1 U6.6 | length 2.9
  Bottom Layer w0.203: C90.1@34.4,73.3 34.4,74.85 34.625,75.075 U6.6@35.625,75.075
NetLED1_1: LED1.1 R1.2 | length 2.2
  Top Layer w0.2: v1(30,4.3) LED1.1@31.05,4.3
  Bottom Layer w0.2: v1(30,4.3) R1.2@31.162,4.3
NetR25_2: R25.2 R26.1 | length 1.5
  Top Layer w0.35: R25.2@73.938,47.4 R26.1@75.462,47.4
NetRN1_8: RN1.8 RN4.5 | length 2.3
  Bottom Layer w0.127: RN1.8@42.89,83.1 45.2,83.1 RN4.5@45.21,83.1
NetRN2_8: RN2.8 RN6.5 | length 2.3
  Bottom Layer w0.127: RN2.8@35.39,83.1 RN6.5@37.675,83.1 RN6.5@37.71,83.1
NEXUS_TCK: HDR_T1.82 U4.A12 | length 73.6
  Top Layer w0.127: v1(36.703,51.191) 36.909,51.191 37.2,50.9 U4.A12@37.2,49.9
  MidLayer3 w0.127: v1(36.703,51.191) 38.438,49.456 38.438,45.73 39.271,44.897 46.022,44.897 46.2,44.719 46.2,38.006 47.2,37.006 47.2,34.095 47.395,33.9 52.8,33.9 53.1,33.9 55,33.9 56.1,35 56.1,38.7 58.1,40.7 58.1,51.5 61.8,55.2 61.8,57.5 61.6,57.7 61.6,60.5 60.5,61.6 v2(60.5,67.7)
  Bottom Layer w0.2: HDR_T1.82@60.5,66.2 v2(60.5,67.7)
NEXUS_TDI: HDR_T1.84 U4.U21 | length 50.2
  Top Layer w0.2: U4.U21@46.2,33.9 v1(46.7,33.4)
  MidLayer3 w0.127: v1(46.7,33.4) 47.2,32.9 52.8,32.9 53.1,32.9 54.7,32.9 56.4,34.6 56.4,38.6 58.4,40.6 58.4,51.4 62.1,55.1 62.1,57.2 62.6,57.7 62.6,60.4 61.3,61.7 v2(61.3,68.3)
  Bottom Layer w0.2: HDR_T1.84@61.3,66.2 v2(61.3,68.3)
NEXUS_TDO: HDR_T1.76 U4.B24 | length 25.2
  Top Layer w0.127: U4.B24@49.2,48.9 49.7,49.4 49.7,50.2 50.3,50.8 50.3,54.5 52.7,56.9 52.7,57.4 58.1,62.8 58.1,67.6 v2(58.1,68.3)
  Bottom Layer w0.2: HDR_T1.76@58.1,66.2 v2(58.1,68.3)
NEXUS_TMS: HDR_T1.80 U4.T24 | length 44.4
  Top Layer w0.2: U4.T24@49.2,34.9 v1(49.7,34.4)
  MidLayer3 w0.127: v1(49.7,34.4) 50,34.4 50.5,34.9 52.8,34.9 53.1,34.9 54.5,34.9 55.8,36.2 55.8,38.8 57.8,40.8 57.8,51.6 60.8,54.6 60.8,57.5 61,57.7 61,60.1 59.7,61.4 v2(59.7,68.3)
  Bottom Layer w0.2: HDR_T1.80@59.7,66.2 v2(59.7,68.3)
NFAULT: R28.2 U6.8 | length 2.6
  Bottom Layer w0.203: U6.8@35.6,76.375 35.6,77 36.2,77.6 R28.2@37.362,77.6
ONE_WIRE.PIO2: U1.6
ONE_WIRE_DB_PB: HDR_B1.79 U4.AA8 | length 49.5
  Top Layer w0.2: v1(32.7,29.4) U4.AA8@33.2,29.9
  MidLayer3 w0.127: v1(32.7,29.4) 32.2,28.9 32.2,23.3 32.2,23 32.2,22.6 31.8,22.2 31.8,17.5 32.2,17.1 32.2,15.8 39.7,8.3 59.3,8.3 59.7,7.9 v2(59.7,6.3)
  Bottom Layer w0.2: v2(59.7,6.3) HDR_B1.79@59.7,8.6
ONE_WIRE_DBID: HDR_T1.92 U1.2 | length 9.2
  Bottom Layer w0.127: HDR_T1.92@64.5,66.2 64.5,68.046 63.8,68.746 63.8,71.6 64.5,72.3 U1.2@66.995,72.3
ONE_WIRE_PIO1: HDR_T1.91 U1.3 | length 26.5
  Top Layer w0.2: v2(64.5,57.3) v2@64.5,57.4
  Top Layer w0.35: v2(64.5,57.3) v2@64.562,57.238
  MidLayer4 w0.203: v2(64.5,57.3) 64.5,59.5 63.9,60.1 63.9,71.1 65.1,72.3 v2(68.8,72.3)
  Bottom Layer w0.127: v2@64.5,57.4 HDR_T1.91@64.5,59.4
  Bottom Layer w0.2: v2(64.5,57.3) 64.5,57.4 HDR_T1.91@64.5,59.4
  Bottom Layer w0.203: U1.3@66.995,73.57 68.33,73.57 68.8,73.1 v2(68.8,72.3)
PROG_B: R15.2 U4.H15 | length 36.8
  Top Layer w0.2: U4.H15@40.2,42.9 v1(40.7,43.4)
  MidLayer4 w0.127: v1(40.2,54.3) 41.2,53.3 41.2,43.9 v1(40.7,43.4)
  Bottom Layer w0.127: R15.2@21.462,53.2 21.5,53.162 v1(21.5,52.4) 22.9,52.4 23.2,52.7 23.2,53.3 23.8,53.9 24.8,53.9 25,53.7 25,52.7 25.2,52.5 26.6,52.5 27.7,53.6 27.7,55.065 27.989,55.354 28.845,55.354 29.435,54.765 37.505,54.765 38.073,55.333 39.167,55.333 v1(40.2,54.3)
REF_1V2: C87.2 U5.10 | length 2.2
  Top Layer w0.4: C87.2@63.65,45.3 63.655,45.294 U5.10@65.852,45.294
REF_CLK: HDR_B1.4 U4.AE10 | length 25.7
  Top Layer w0.127: v1(35.024,19.788) 35.024,20.382 34.7,20.706 34.7,23 34.7,23.3 34.7,25.4 U4.AE10@35.2,25.9
  MidLayer1 w0.127: v2(29.3,17.5) 29.3,16.9 29.9,16.3 38.4,16.3 39.4,17.3 39.4,18 v1(38.7,18.7)
  MidLayer4 w0.127: v1(35.024,19.788) 36.112,18.7 v1(38.7,18.7)
  Bottom Layer w0.2: HDR_B1.4@29.3,15.4 v2(29.3,17.5)
RS232_CTS: HDR_T1.22 U4.B14 | length 23.7
  Top Layer w0.127: v2(36.5,67.7) 36.5,62.8 40.2,59.1 40.2,57.7 39.9,57.4 39.9,56.918 38.209,55.227 38.209,54.298 v1(38.76,53.746) ; v1(39.04,52.045) 39.455,52.045 39.7,51.8 39.7,51.5 39.7,49.4 U4.B14@39.2,48.9
  MidLayer1 w0.127: v1(38.76,53.746) 38.76,52.847 39.04,52.568 v1(39.04,52.045)
  Bottom Layer w0.2: HDR_T1.22@36.5,66.2 v2(36.5,67.7)
RS232_RTS: HDR_T1.18 U4.B13 | length 22.4
  Top Layer w0.127: v2(34.9,67.7) 34.9,62.8 38.6,59.1 38.6,57.7 38.3,57.4 38.3,57.2 37.7,56.6 37.7,51.8 37.7,51.5 37.7,49.4 U4.B13@38.2,48.9
  Bottom Layer w0.2: HDR_T1.18@34.9,66.2 v2(34.9,67.7)
RS232_RX: HDR_T1.24 U4.A16 | length 22.5
  Top Layer w0.127: v2(37.3,68.3) 37.3,62.6 40.8,59.1 40.8,57.7 41.3,57.2 41.3,53 40.8,52.5 40.8,51.8 40.8,51.5 40.8,50.7 41.2,50.3 U4.A16@41.2,49.9
  Bottom Layer w0.2: HDR_T1.24@37.3,66.2 v2(37.3,68.3)
RS232_TX: HDR_T1.20 U4.A15 | length 24.2
  Top Layer w0.127: v2(35.7,68.3) 35.7,62.6 39.2,59.1 39.2,57.7 39.5,57.4 39.5,57 37.955,55.455 37.955,53.51 38.811,52.654 39.695,52.654 40,52.349 40,51.8 40,51.5 40,50.5 40.2,50.3 U4.A15@40.2,49.9
  Bottom Layer w0.2: HDR_T1.20@35.7,66.2 v2(35.7,68.3)
SCL: HDR_B1.5 U4.AA7 | length 25.4
  Top Layer w0.2: v1(31.7,29.4) U4.AA7@32.2,29.9
  MidLayer3 w0.127: v2(30.1,7.1) 30.1,16.1 30.6,16.6 30.6,17.1 30.3,17.4 30.3,23 30.3,23.3 30.3,25.2 31.2,26.1 31.2,28.9 v1(31.7,29.4)
  Bottom Layer w0.2: v2(30.1,7.1) HDR_B1.5@30.1,8.6
SDA: HDR_B1.3 U4.AA3 | length 30
  Top Layer w0.2: v1(27.7,29.4) U4.AA3@28.2,29.9
  MidLayer1 w0.127: v1(27.7,29.4) 27.5,29.4 27,28.9 25.5,28.9 23.3,26.7 23.3,16.041 27.095,12.246 27.354,12.246 29.3,10.3 v2(29.3,7.1)
  Bottom Layer w0.2: v2(29.3,7.1) HDR_B1.3@29.3,8.6
SLEEP_N: HDR_T1.93
SPI_CLK: HDR_T1.46 U4.D12 | length 27.9
  Top Layer w0.2: v1(36.7,47.4) U4.D12@37.2,46.9
  MidLayer2 w0.127: v1(36.7,47.4) 37.2,47.9 37.2,48.605 38.176,49.581 39.458,49.581 40.157,50.28 40.157,53.057 42.7,55.6 43.5,55.6 44.2,56.3 44.2,57.5 43.9,57.8 43.9,58.3 46.1,60.5 v2(46.1,67.7)
  Bottom Layer w0.2: HDR_T1.46@46.1,66.2 v2(46.1,67.7)
SPI_DIN: HDR_T1.44 U4.C11 | length 27.5
  Top Layer w0.2: v1(35.7,48.4) U4.C11@36.2,47.9
  MidLayer2 w0.127: v1(35.7,48.4) 36.2,48.9 36.2,51.5 36.2,51.8 36.2,53.3 39.2,56.3 39.6,56.7 40.8,56.7 41.9,57.8 41.9,58.9 43.3,60.3 43.3,66.3 v2(45.3,68.3)
  Bottom Layer w0.2: HDR_T1.44@45.3,66.2 v2(45.3,68.3)
  Bottom Layer w0.381: v1(35.7,48.4) v1@35.808,48.4
SPI_DOUT: HDR_T1.50 U4.G10 | length 33.3
  Top Layer w0.2: v1(34.7,44.4) U4.G10@35.2,43.9
  MidLayer2 w0.127: v1(34.7,44.4) 35.3,44.4 35.8,44.9 38.1,44.9 38.5,45.3 38.5,47.904 40.7,50.104 40.7,52.7 43,55 44,55 45.8,56.8 45.8,57.5 45.6,57.7 45.6,58.2 47.7,60.3 v2(47.7,67.7)
  Bottom Layer w0.2: HDR_T1.50@47.7,66.2 v2(47.7,67.7)
SPI_MODE: HDR_T1.52 U4.E14 | length 29
  Top Layer w0.2: U4.E14@39.2,45.9 v1(39.7,46.4)
  MidLayer2 w0.127: v1(39.7,46.4) 40.2,46.9 40.2,48.793 41.2,49.793 41.2,51.5 41.2,51.8 41.2,52.8 43.1,54.7 44.2,54.7 44.5,55 45.4,55.9 46.3,56.8 46.3,57.4 48.5,59.6 v2(48.5,68.3)
  Bottom Layer w0.2: HDR_T1.52@48.5,66.2 v2(48.5,68.3)
SPI_SEL: HDR_T1.48 U4.E13 | length 29
  Top Layer w0.2: v1(37.7,46.4) U4.E13@38.2,45.9
  MidLayer2 w0.127: v1(37.7,46.4) 38.2,46.9 38.2,47.964 40.446,50.21 40.446,52.846 42.2,54.6 42.9,55.3 43.7,55.3 44.8,56.4 44.8,57.5 45.1,57.8 45.1,58.1 46.9,59.9 v2(46.9,68.3)
  Bottom Layer w0.2: HDR_T1.48@46.9,66.2 v2(46.9,68.3)
SRAM1_A0: U4.V22 U10.1 | length 26.5
  Top Layer w0.2: U4.V22@47.2,32.9 v1(47.7,32.4)
  MidLayer2 w0.127: v1(47.7,32.4) 48.2,31.9 52.8,31.9 53.1,31.9 53.9,31.9 56.1,29.7 56.1,25.4 63,18.5 v1(64.1,18.5)
  Bottom Layer w0.127: U10.1@62.952,18.5 v1(64.1,18.5)
SRAM1_A1: U4.U22 U10.2 | length 28.6
  Top Layer w0.2: U4.U22@47.2,33.9 v1(47.7,33.4)
  MidLayer2 w0.127: v1(47.7,33.4) 48.2,32.9 52.8,32.9 53.1,32.9 55.9,32.9 56.7,32.1 56.7,26.4 63.8,19.3 v1(64.7,19.3)
  Bottom Layer w0.127: U10.2@62.952,19.3 v1(64.7,19.3)
SRAM1_A2: U4.P23 U10.3 | length 29.5
  Top Layer w0.2: U4.P23@48.2,36.9 v1(48.7,36.4)
  MidLayer1 w0.127: v1(48.7,36.4) 48.2,35.9 48.2,27 48.3,26.9 48.9,26.9 49.2,26.6 49.2,25.8 50.1,24.9 51.2,24.9 51.7,24.4 52.8,24.4 53.1,24.4 53.8,24.4 54,24.2 54,23.5 53.8,23.3 v1(53.8,22.8)
  Bottom Layer w0.127: v1(53.8,22.8) 56.5,20.1 U10.3@62.952,20.1
SRAM1_A3: U4.Y17 U10.4 | length 33.5
  Top Layer w0.2: U4.Y17@42.2,30.9 v1(42.7,30.4)
  MidLayer4 w0.127: v1(42.7,30.4) 43.2,29.9 43.2,23.3 43.2,23 43.2,22.3 45.4,20.1 48.705,20.1 49.505,20.9 v1(64.7,20.9)
  Bottom Layer w0.127: U10.4@62.952,20.9 v1(64.7,20.9)
SRAM1_A4: U4.Y18 U10.5 | length 31.6
  Top Layer w0.2: U4.Y18@43.2,30.9 v1(43.7,30.4)
  MidLayer4 w0.127: v1(43.7,30.4) 44.2,29.9 44.2,23.3 44.2,23 44.2,22 45.846,20.354 48.209,20.354 49.555,21.7 v1(64.1,21.7)
  Bottom Layer w0.127: U10.5@62.952,21.7 v1(64.1,21.7)
SRAM1_A5: U4.V20 U10.18 | length 20.9
  Top Layer w0.2: U4.V20@45.2,32.9 v1(45.7,32.4)
  MidLayer4 w0.127: v1(45.7,32.4) 46.2,31.9 52.8,31.9 53.1,31.9 53.8,31.9 54.1,31.6 61.5,31.6 62,32.1 v1(64.105,32.1)
  Bottom Layer w0.127: U10.18@62.952,32.1 v1(64.105,32.1) v1@64.205,32.1
SRAM1_A6: U4.U20 U10.19 | length 21.8
  Top Layer w0.2: U4.U20@45.2,33.9 v1(45.7,33.4)
  MidLayer4 w0.127: v1(45.7,33.4) 46.2,32.9 52.8,32.9 53.1,32.9 53.8,32.9 v1(64.7,32.9)
  Bottom Layer w0.127: U10.19@62.952,32.9 v1(64.7,32.9) v1@64.8,32.9
SRAM1_A7: U4.T20 U10.20 | length 20.7
  Top Layer w0.2: U4.T20@45.2,34.9 v1(45.7,34.4)
  MidLayer4 w0.127: v1(45.7,34.4) 46.1,33.9 50,33.9 52.8,33.9 53.1,33.9 54.5,33.9 54.7,33.7 62.4,33.7 v1(64.105,33.7)
  Bottom Layer w0.127: U10.20@62.952,33.7 v1(64.105,33.7) v1@64.205,33.7
SRAM1_A8: U4.R20 U10.21 | length 22.1
  Top Layer w0.2: U4.R20@45.2,35.9 v1(45.7,35.4)
  MidLayer4 w0.127: v1(45.7,35.4) 46.2,34.9 52.8,34.9 53.1,34.9 56,34.9 56.4,34.5 v1(64.7,34.5)
  Bottom Layer w0.127: U10.21@62.8,34.5 U10.21@62.952,34.5 v1(64.7,34.5) v1@64.8,34.5
SRAM1_A9: U4.P20 U10.22 | length 20.7
  Top Layer w0.2: U4.P20@45.2,36.9 v1(45.7,36.4)
  MidLayer4 w0.127: v1@45.75,36.4 46.2,35.9 52.8,35.9 53.1,35.9 55.9,35.9 56.5,35.3 v1(64.105,35.3)
  Bottom Layer w0.127: U10.22@62.952,35.3 v1(64.105,35.3)
SRAM1_A10: U4.V21 U10.23 | length 31.3
  Top Layer w0.2: U4.V21@46.2,32.9 v1(46.7,32.4)
  MidLayer3 w0.127: v1(46.7,32.4) 47.2,31.9 52.8,31.9 53.1,31.9 53.7,31.9 54.3,31.3 57.8,31.3 61.8,35.3 63.405,35.3 63.905,35.8 64.305,35.8 64.805,35.3 ; 64.8,35.3 64.805,35.3 ; v1(73.2,35.3) 71.5,35.3 71,35.8 70.6,35.8 70.1,35.3 64.805,35.3
  Bottom Layer w0.127: v1(73.2,35.3) U10.23@74.352,35.3
SRAM1_A11: U4.W21 U10.24 | length 30.9
  Top Layer w0.2: U4.W21@46.2,31.9 v1(46.7,31.4)
  MidLayer3 w0.127: v1(46.7,31.4) 47.2,30.9 52.8,30.9 53.1,30.9 59.4,30.9 63,34.5 64,34.5 64.5,35 64.9,35 65.4,34.5 69.4,34.5 69.9,35 70.3,35 70.8,34.5 v1(73.2,34.5)
  Bottom Layer w0.127: v1(73.2,34.5) U10.24@74.352,34.5
SRAM1_A12: U4.Y21 U10.25 | length 31
  Top Layer w0.2: U4.Y21@46.2,30.9 v1(46.7,30.4)
  MidLayer3 w0.127: v1(46.7,30.4) 47.2,29.9 52.8,29.9 53.1,29.9 59.2,29.9 63,33.7 63.405,33.7 63.905,34.2 64.305,34.2 64.805,33.7 70.1,33.7 70.6,34.2 71,34.2 71.5,33.7 v1(73.2,33.7)
  Bottom Layer w0.127: v1(73.2,33.7) U10.25@74.352,33.7
SRAM1_A13: U4.AA20 U10.26 | length 46.6
  Top Layer w0.2: U4.AA20@45.2,29.9 v1(45.7,29.4)
  MidLayer3 w0.127: v1(45.7,29.4) 46.2,28.9 46.2,23.3 46.2,23 46.2,20.1 46.5,19.8 53,19.8 58.9,25.7 58.9,28.8 63,32.9 64,32.9 64.5,33.4 64.9,33.4 65.4,32.9 69.4,32.9 69.9,33.4 70.3,33.4 70.8,32.9 v1(73.2,32.9)
  Bottom Layer w0.127: v1(73.2,32.9) U10.26@74.352,32.9
SRAM1_A14: U4.AA19 U10.27 | length 47.1
  Top Layer w0.2: U4.AA19@44.2,29.9 v1(44.7,29.4)
  MidLayer3 w0.127: v1(44.7,29.4) 45.2,28.9 45.2,23.3 45.2,23 45.2,20.6 46.3,19.5 53.2,19.5 60.1,26.4 60.1,29.3 62.9,32.1 63.405,32.1 63.905,32.6 64.305,32.6 64.805,32.1 70.1,32.1 70.6,32.6 71,32.6 71.5,32.1 v1(73.2,32.1)
  Bottom Layer w0.127: v1(73.2,32.1) U10.27@74.352,32.1
SRAM1_A15: U4.AC21 U10.42 | length 34.5
  Top Layer w0.2: U4.AC21@46.2,27.9 v1(46.7,27.4)
  MidLayer1 w0.127: v1(46.7,27.4) 47.2,26.9 47.2,26.1 46.8,25.7 46.8,23.3 46.8,23 46.8,22.6 48.7,20.7 64.2,20.7 64.8,20.1 v1(73.2,20.1)
  Bottom Layer w0.127: v1(73.2,20.1) U10.42@74.352,20.1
